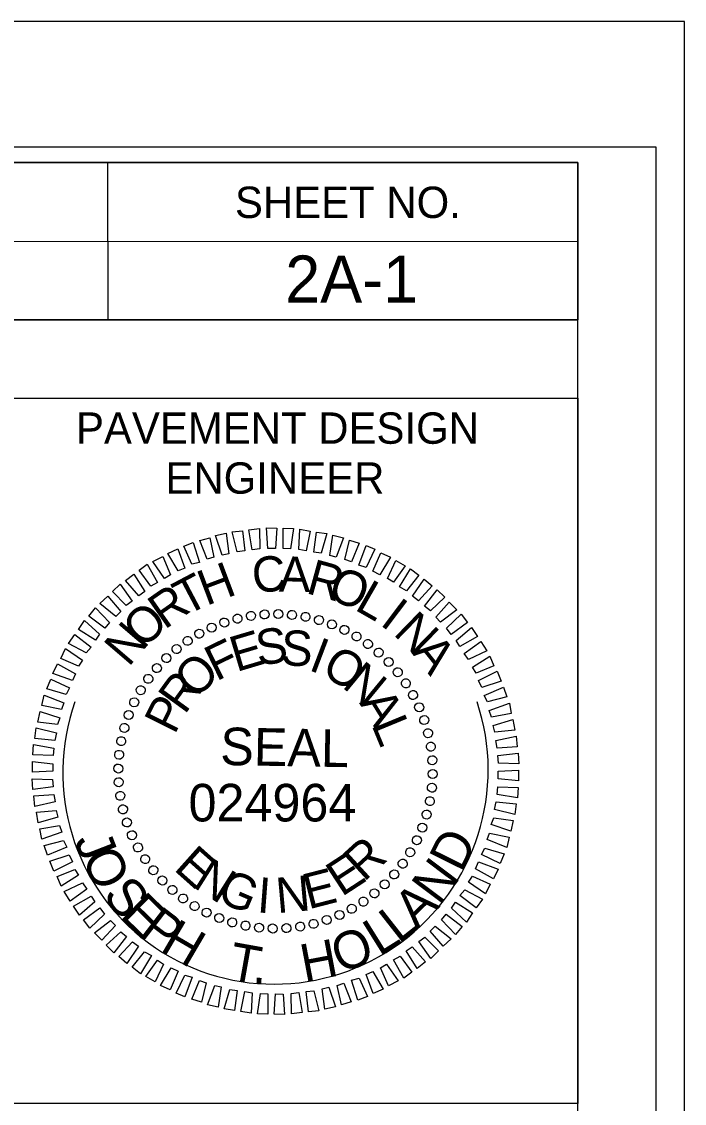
# Model space of a CAD drawing. Extents: x 1640342 to 1730599, y 538663 to 843747.
# Drawn here: x 1730156.25 to 1730177.39, y 540321.41 to 540355.92 of the extents above; entities that cross this region are included whole.
import ezdxf

# ---------------------------------------------------------------- set-up
doc = ezdxf.new("R2010")
doc.units = 0
for name, color, linetype in [('Sheet Data Field CELL', 7, 'Continuous'), ('Sheet PE Seal Cell', 7, 'Continuous'), ('Sheet Plan CELL', 7, 'Continuous'), ('Sheet Plot Border Inside CELL', 7, 'Continuous'), ('Sheet Plot Border Outside CELL', 7, 'Continuous')]:
    doc.layers.add(name, color=color, linetype=linetype)

msp = doc.modelspace()

# ---------------------------------------------------------------- linework, layer by layer
at = {"layer": 'Sheet PE Seal Cell'}
for p, q in [((1730163.569, 540336.956), (1730163.569, 540336.956)), ((1730163.999, 540337.016), (1730163.999, 540337.016)), ((1730164.439, 540337.026), (1730164.439, 540337.026)), ((1730164.879, 540336.996), (1730164.879, 540336.996)), ((1730165.309, 540336.926), (1730165.309, 540336.926)), ((1730162.309, 540336.596), (1730162.309, 540336.596)), ((1730162.709, 540336.756), (1730162.709, 540336.756)), ((1730163.129, 540336.876), (1730163.129, 540336.876)), ((1730165.729, 540336.836), (1730165.729, 540336.836)), ((1730166.149, 540336.696), (1730166.149, 540336.696)), ((1730161.919, 540336.396), (1730161.919, 540336.396)), ((1730166.549, 540336.516), (1730166.549, 540336.516)), ((1730166.939, 540336.316), (1730166.939, 540336.316)), ((1730161.189, 540335.916), (1730161.189, 540335.916)), ((1730161.539, 540336.166), (1730161.539, 540336.166)), ((1730167.299, 540336.066), (1730167.299, 540336.066)), ((1730160.859, 540335.616), (1730160.859, 540335.616)), ((1730167.649, 540335.796), (1730167.649, 540335.796)), ((1730160.559, 540335.306), (1730160.559, 540335.306)), ((1730167.959, 540335.496), (1730167.959, 540335.496)), ((1730160.289, 540334.956), (1730160.289, 540334.956)), ((1730168.259, 540335.166), (1730168.259, 540335.166)), ((1730160.039, 540334.596), (1730160.039, 540334.596)), ((1730168.509, 540334.816), (1730168.509, 540334.816)), ((1730159.839, 540334.206), (1730159.839, 540334.206)), ((1730168.739, 540334.436), (1730168.739, 540334.436)), ((1730168.939, 540334.046), (1730168.939, 540334.046)), ((1730159.659, 540333.806), (1730159.659, 540333.806)), ((1730169.099, 540333.646), (1730169.099, 540333.646)), ((1730159.519, 540333.386), (1730159.519, 540333.386)), ((1730169.219, 540333.226), (1730169.219, 540333.226)), ((1730159.429, 540332.966), (1730159.429, 540332.966)), ((1730169.299, 540332.786), (1730169.299, 540332.786)), ((1730159.359, 540332.536), (1730159.359, 540332.536)), ((1730159.329, 540332.096), (1730159.329, 540332.096)), ((1730169.359, 540332.356), (1730169.359, 540332.356)), ((1730169.369, 540331.916), (1730169.369, 540331.916)), ((1730159.339, 540331.656), (1730159.339, 540331.656)), ((1730169.339, 540331.476), (1730169.339, 540331.476)), ((1730159.399, 540331.226), (1730159.399, 540331.226)), ((1730159.479, 540330.786), (1730159.479, 540330.786)), ((1730169.269, 540331.046), (1730169.269, 540331.046)), ((1730159.599, 540330.366), (1730159.599, 540330.366)), ((1730169.179, 540330.626), (1730169.179, 540330.626)), ((1730169.039, 540330.206), (1730169.039, 540330.206)), ((1730159.759, 540329.966), (1730159.759, 540329.966)), ((1730168.859, 540329.806), (1730168.859, 540329.806)), ((1730159.959, 540329.576), (1730159.959, 540329.576)), ((1730168.659, 540329.416), (1730168.659, 540329.416)), ((1730160.189, 540329.196), (1730160.189, 540329.196)), ((1730168.409, 540329.056), (1730168.409, 540329.056)), ((1730160.439, 540328.846), (1730160.439, 540328.846)), ((1730168.139, 540328.706), (1730168.139, 540328.706)), ((1730160.739, 540328.516), (1730160.739, 540328.516)), ((1730167.839, 540328.396), (1730167.839, 540328.396)), ((1730161.049, 540328.216), (1730161.049, 540328.216)), ((1730161.399, 540327.946), (1730161.399, 540327.946)), ((1730167.509, 540328.096), (1730167.509, 540328.096)), ((1730161.759, 540327.696), (1730161.759, 540327.696)), ((1730166.779, 540327.616), (1730166.779, 540327.616)), ((1730167.159, 540327.846), (1730167.159, 540327.846)), ((1730162.149, 540327.496), (1730162.149, 540327.496)), ((1730162.549, 540327.316), (1730162.549, 540327.316)), ((1730165.989, 540327.256), (1730165.989, 540327.256)), ((1730166.389, 540327.416), (1730166.389, 540327.416)), ((1730162.969, 540327.176), (1730162.969, 540327.176)), ((1730163.389, 540327.086), (1730163.389, 540327.086)), ((1730163.819, 540327.016), (1730163.819, 540327.016)), ((1730164.259, 540326.986), (1730164.259, 540326.986)), ((1730164.699, 540326.996), (1730164.699, 540326.996)), ((1730165.129, 540327.056), (1730165.129, 540327.056)), ((1730165.569, 540327.136), (1730165.569, 540327.136))]:
    msp.add_line(p, q, dxfattribs=at)
for points in [[(1730163.129, 540339.006), (1730162.969, 540339.646), (1730163.299, 540339.676), (1730163.369, 540339.036)], [(1730163.609, 540339.066), (1730163.499, 540339.706), (1730163.839, 540339.746), (1730163.849, 540339.096)], [(1730164.109, 540339.116), (1730164.059, 540339.766), (1730164.389, 540339.756), (1730164.349, 540339.106)], [(1730164.589, 540339.106), (1730164.589, 540339.756), (1730164.919, 540339.746), (1730164.829, 540339.096)], [(1730165.089, 540339.076), (1730165.129, 540339.726), (1730165.459, 540339.666), (1730165.329, 540339.036)], [(1730162.169, 540338.766), (1730161.939, 540339.366), (1730162.249, 540339.456), (1730162.379, 540338.836)], [(1730162.649, 540338.896), (1730162.439, 540339.526), (1730162.779, 540339.596), (1730162.859, 540338.946)], [(1730165.569, 540338.996), (1730165.659, 540339.636), (1730165.989, 540339.586), (1730165.809, 540338.966)], [(1730166.079, 540338.886), (1730166.179, 540339.536), (1730166.519, 540339.456), (1730166.289, 540338.836)], [(1730166.559, 540338.756), (1730166.709, 540339.376), (1730167.019, 540339.276), (1730166.769, 540338.686)], [(1730161.239, 540338.396), (1730160.919, 540338.956), (1730161.229, 540339.096), (1730161.459, 540338.486)], [(1730161.679, 540338.606), (1730161.419, 540339.186), (1730161.719, 540339.306), (1730161.929, 540338.666)], [(1730167.009, 540338.576), (1730167.239, 540339.206), (1730167.519, 540339.086), (1730167.239, 540338.506)], [(1730160.809, 540338.156), (1730160.439, 540338.696), (1730160.749, 540338.856), (1730160.999, 540338.276)], [(1730167.459, 540338.386), (1730167.709, 540338.976), (1730168.019, 540338.836), (1730167.679, 540338.276)], [(1730167.919, 540338.156), (1730168.189, 540338.726), (1730168.489, 540338.556), (1730168.109, 540338.036)], [(1730159.989, 540337.606), (1730159.559, 540338.086), (1730159.829, 540338.296), (1730160.179, 540337.736)], [(1730160.369, 540337.906), (1730159.999, 540338.416), (1730160.259, 540338.606), (1730160.589, 540338.026)], [(1730168.309, 540337.886), (1730168.659, 540338.466), (1730168.919, 540338.256), (1730168.529, 540337.766)], [(1730159.589, 540337.296), (1730159.149, 540337.736), (1730159.389, 540337.976), (1730159.779, 540337.436)], [(1730168.719, 540337.586), (1730169.089, 540338.136), (1730169.349, 540337.916), (1730168.909, 540337.446)], [(1730169.099, 540337.276), (1730169.509, 540337.796), (1730169.749, 540337.556), (1730169.289, 540337.126)], [(1730159.259, 540336.946), (1730158.749, 540337.356), (1730158.999, 540337.586), (1730159.419, 540337.106)], [(1730169.459, 540336.926), (1730169.889, 540337.396), (1730170.129, 540337.156), (1730169.609, 540336.766)], [(1730158.909, 540336.566), (1730158.389, 540336.956), (1730158.609, 540337.216), (1730159.049, 540336.746)], [(1730169.809, 540336.566), (1730170.269, 540337.016), (1730170.479, 540336.746), (1730169.949, 540336.366)], [(1730158.609, 540336.186), (1730158.069, 540336.526), (1730158.259, 540336.816), (1730158.739, 540336.376)], [(1730170.109, 540336.176), (1730170.599, 540336.596), (1730170.789, 540336.306), (1730170.229, 540335.986)], [(1730158.309, 540335.786), (1730157.749, 540336.086), (1730157.949, 540336.366), (1730158.469, 540335.966)], [(1730158.069, 540335.356), (1730157.499, 540335.606), (1730157.649, 540335.916), (1730158.189, 540335.546)], [(1730170.369, 540335.766), (1730170.899, 540336.146), (1730171.089, 540335.846), (1730170.509, 540335.566)], [(1730170.629, 540335.326), (1730171.189, 540335.676), (1730171.319, 540335.366), (1730170.749, 540335.136)], [(1730157.869, 540334.896), (1730157.249, 540335.126), (1730157.399, 540335.436), (1730157.969, 540335.116)], [(1730170.829, 540334.896), (1730171.419, 540335.196), (1730171.549, 540334.876), (1730170.929, 540334.676)], [(1730157.669, 540334.456), (1730157.049, 540334.636), (1730157.179, 540334.946), (1730157.779, 540334.666)], [(1730171.009, 540334.426), (1730171.619, 540334.686), (1730171.729, 540334.376), (1730171.109, 540334.216)], [(1730157.519, 540333.976), (1730156.899, 540334.106), (1730156.969, 540334.436), (1730157.599, 540334.186)], [(1730171.169, 540333.946), (1730171.809, 540334.176), (1730171.869, 540333.846), (1730171.239, 540333.736)], [(1730157.389, 540333.496), (1730156.769, 540333.576), (1730156.839, 540333.916), (1730157.469, 540333.706)], [(1730171.289, 540333.466), (1730171.919, 540333.656), (1730171.979, 540333.316), (1730171.349, 540333.256)], [(1730157.309, 540332.986), (1730156.669, 540333.046), (1730156.709, 540333.386), (1730157.359, 540333.226)], [(1730171.379, 540332.986), (1730172.029, 540333.126), (1730172.059, 540332.786), (1730171.419, 540332.746)], [(1730157.259, 540332.506), (1730156.609, 540332.526), (1730156.629, 540332.856), (1730157.279, 540332.746)], [(1730171.439, 540332.506), (1730172.089, 540332.586), (1730172.109, 540332.246), (1730171.459, 540332.266)], [(1730157.249, 540332.006), (1730156.599, 540331.976), (1730156.599, 540332.316), (1730157.249, 540332.246)], [(1730157.259, 540331.506), (1730156.609, 540331.426), (1730156.589, 540331.766), (1730157.239, 540331.746)], [(1730171.449, 540332.006), (1730172.099, 540332.036), (1730172.099, 540331.696), (1730171.449, 540331.766)], [(1730171.439, 540331.506), (1730172.089, 540331.486), (1730172.069, 540331.156), (1730171.419, 540331.266)], [(1730157.319, 540331.026), (1730156.669, 540330.886), (1730156.639, 540331.226), (1730157.279, 540331.266)], [(1730157.409, 540330.546), (1730156.779, 540330.356), (1730156.719, 540330.696), (1730157.349, 540330.756)], [(1730171.389, 540331.026), (1730172.029, 540330.966), (1730171.989, 540330.626), (1730171.339, 540330.786)], [(1730171.309, 540330.516), (1730171.929, 540330.436), (1730171.859, 540330.096), (1730171.229, 540330.306)], [(1730157.529, 540330.066), (1730156.889, 540329.836), (1730156.829, 540330.166), (1730157.459, 540330.276)], [(1730171.179, 540330.036), (1730171.799, 540329.906), (1730171.729, 540329.576), (1730171.099, 540329.826)], [(1730157.689, 540329.586), (1730157.079, 540329.326), (1730156.969, 540329.636), (1730157.589, 540329.796)], [(1730157.869, 540329.116), (1730157.279, 540328.816), (1730157.149, 540329.136), (1730157.769, 540329.336)], [(1730171.029, 540329.556), (1730171.649, 540329.376), (1730171.519, 540329.066), (1730170.919, 540329.346)], [(1730170.829, 540329.116), (1730171.449, 540328.886), (1730171.299, 540328.576), (1730170.729, 540328.896)], [(1730158.069, 540328.686), (1730157.509, 540328.336), (1730157.379, 540328.646), (1730157.949, 540328.876)], [(1730170.629, 540328.656), (1730171.199, 540328.406), (1730171.049, 540328.096), (1730170.509, 540328.466)], [(1730158.329, 540328.246), (1730157.799, 540327.866), (1730157.609, 540328.166), (1730158.189, 540328.446)], [(1730158.589, 540327.836), (1730158.099, 540327.416), (1730157.909, 540327.706), (1730158.469, 540328.026)], [(1730170.389, 540328.226), (1730170.949, 540327.926), (1730170.749, 540327.646), (1730170.229, 540328.046)], [(1730158.889, 540327.446), (1730158.429, 540326.996), (1730158.219, 540327.266), (1730158.749, 540327.646)], [(1730170.089, 540327.826), (1730170.629, 540327.486), (1730170.439, 540327.196), (1730169.959, 540327.636)], [(1730169.789, 540327.446), (1730170.309, 540327.056), (1730170.089, 540326.796), (1730169.649, 540327.266)], [(1730159.239, 540327.086), (1730158.809, 540326.616), (1730158.569, 540326.856), (1730159.089, 540327.246)], [(1730169.439, 540327.066), (1730169.949, 540326.656), (1730169.699, 540326.426), (1730169.279, 540326.906)], [(1730159.599, 540326.736), (1730159.189, 540326.216), (1730158.949, 540326.456), (1730159.409, 540326.886)], [(1730159.979, 540326.426), (1730159.609, 540325.876), (1730159.349, 540326.096), (1730159.789, 540326.566)], [(1730169.109, 540326.716), (1730169.549, 540326.276), (1730169.309, 540326.036), (1730168.919, 540326.576)], [(1730160.389, 540326.126), (1730160.039, 540325.546), (1730159.779, 540325.756), (1730160.169, 540326.246)], [(1730168.709, 540326.406), (1730169.139, 540325.926), (1730168.869, 540325.716), (1730168.519, 540326.276)], [(1730160.779, 540325.856), (1730160.509, 540325.286), (1730160.209, 540325.456), (1730160.589, 540325.976)], [(1730168.329, 540326.106), (1730168.699, 540325.596), (1730168.439, 540325.406), (1730168.109, 540325.986)], [(1730161.239, 540325.626), (1730160.989, 540325.036), (1730160.679, 540325.176), (1730161.019, 540325.736)], [(1730167.459, 540325.616), (1730167.779, 540325.056), (1730167.469, 540324.916), (1730167.239, 540325.526)], [(1730167.889, 540325.856), (1730168.259, 540325.316), (1730167.949, 540325.156), (1730167.699, 540325.736)], [(1730161.689, 540325.436), (1730161.459, 540324.806), (1730161.179, 540324.926), (1730161.459, 540325.506)], [(1730162.139, 540325.256), (1730161.989, 540324.636), (1730161.679, 540324.736), (1730161.929, 540325.326)], [(1730166.529, 540325.246), (1730166.759, 540324.646), (1730166.449, 540324.556), (1730166.319, 540325.176)], [(1730167.019, 540325.406), (1730167.279, 540324.826), (1730166.979, 540324.706), (1730166.769, 540325.346)], [(1730162.619, 540325.126), (1730162.519, 540324.476), (1730162.179, 540324.556), (1730162.409, 540325.176)], [(1730163.129, 540325.016), (1730163.039, 540324.376), (1730162.709, 540324.426), (1730162.889, 540325.046)], [(1730163.609, 540324.936), (1730163.569, 540324.286), (1730163.239, 540324.346), (1730163.369, 540324.976)], [(1730164.109, 540324.906), (1730164.109, 540324.256), (1730163.779, 540324.266), (1730163.869, 540324.916)], [(1730164.589, 540324.896), (1730164.639, 540324.246), (1730164.309, 540324.256), (1730164.349, 540324.906)], [(1730165.089, 540324.946), (1730165.199, 540324.306), (1730164.859, 540324.266), (1730164.849, 540324.916)], [(1730165.569, 540325.006), (1730165.729, 540324.366), (1730165.399, 540324.336), (1730165.329, 540324.976)], [(1730166.049, 540325.116), (1730166.259, 540324.486), (1730165.919, 540324.416), (1730165.839, 540325.066)]]:
    msp.add_lwpolyline(points, close=True, dxfattribs=at)
for centre, major_axis in [((1730163.136, 540336.873), (-0.035, 0.14)), ((1730163.565, 540336.96), (-0.023, 0.142)), ((1730163.999, 540337.009), (-0.01, 0.144)), ((1730164.437, 540337.021), (0.003, 0.144)), ((1730164.874, 540336.994), (0.015, 0.143)), ((1730165.306, 540336.93), (0.027, 0.141)), ((1730165.732, 540336.827), (0.04, 0.138)), ((1730162.309, 540336.588), (-0.059, 0.132)), ((1730162.716, 540336.748), (-0.047, 0.136)), ((1730166.147, 540336.689), (0.052, 0.134)), ((1730166.548, 540336.514), (0.063, 0.129)), ((1730161.544, 540336.164), (-0.081, 0.119)), ((1730161.918, 540336.393), (-0.07, 0.126)), ((1730166.933, 540336.305), (0.074, 0.123)), ((1730167.298, 540336.064), (0.085, 0.116)), ((1730161.193, 540335.904), (-0.091, 0.112)), ((1730167.64, 540335.791), (0.094, 0.109)), ((1730160.865, 540335.614), (-0.1, 0.104)), ((1730167.958, 540335.49), (0.104, 0.1)), ((1730160.564, 540335.296), (-0.109, 0.094)), ((1730168.247, 540335.162), (0.112, 0.091)), ((1730160.291, 540334.954), (-0.116, 0.085)), ((1730168.508, 540334.811), (0.119, 0.081)), ((1730160.05, 540334.589), (-0.123, 0.074)), ((1730168.736, 540334.438), (0.126, 0.07)), ((1730159.841, 540334.205), (-0.129, 0.063)), ((1730168.932, 540334.046), (0.132, 0.059)), ((1730159.666, 540333.803), (-0.134, 0.052)), ((1730159.528, 540333.388), (-0.138, 0.04)), ((1730169.092, 540333.639), (0.136, 0.047)), ((1730159.425, 540332.963), (-0.141, 0.027)), ((1730169.216, 540333.219), (0.14, 0.035)), ((1730169.304, 540332.79), (0.142, 0.023)), ((1730159.361, 540332.53), (-0.143, 0.015)), ((1730169.353, 540332.356), (0.144, 0.01)), ((1730159.334, 540332.093), (-0.144, 0.003)), ((1730159.346, 540331.656), (-0.144, -0.01)), ((1730169.365, 540331.918), (0.144, -0.003)), ((1730169.338, 540331.481), (0.143, -0.015)), ((1730159.395, 540331.221), (-0.142, -0.023)), ((1730169.273, 540331.049), (0.141, -0.027)), ((1730159.482, 540330.792), (-0.14, -0.035)), ((1730169.171, 540330.623), (0.138, -0.04)), ((1730159.607, 540330.373), (-0.136, -0.047)), ((1730169.032, 540330.208), (0.134, -0.052)), ((1730159.767, 540329.965), (-0.132, -0.059)), ((1730159.962, 540329.574), (-0.126, -0.07)), ((1730168.858, 540329.807), (0.129, -0.063)), ((1730160.191, 540329.201), (-0.119, -0.081)), ((1730168.649, 540329.422), (0.123, -0.074)), ((1730160.451, 540328.849), (-0.112, -0.091)), ((1730168.407, 540329.057), (0.116, -0.085)), ((1730160.741, 540328.521), (-0.104, -0.1)), ((1730168.135, 540328.715), (0.109, -0.094)), ((1730161.059, 540328.22), (-0.094, -0.109)), ((1730167.834, 540328.397), (0.1, -0.104)), ((1730161.401, 540327.948), (-0.085, -0.116)), ((1730167.154, 540327.847), (0.081, -0.119)), ((1730167.506, 540328.108), (0.091, -0.112)), ((1730161.766, 540327.706), (-0.074, -0.123)), ((1730162.15, 540327.497), (-0.063, -0.129)), ((1730166.781, 540327.619), (0.07, -0.126)), ((1730162.552, 540327.323), (-0.052, -0.134)), ((1730162.967, 540327.184), (-0.04, -0.138)), ((1730165.563, 540327.139), (0.035, -0.14)), ((1730165.982, 540327.263), (0.047, -0.136)), ((1730166.39, 540327.423), (0.059, -0.132)), ((1730163.392, 540327.082), (-0.027, -0.141)), ((1730163.825, 540327.017), (-0.015, -0.143)), ((1730164.262, 540326.99), (-0.003, -0.144)), ((1730164.699, 540327.002), (0.01, -0.144)), ((1730165.134, 540327.051), (0.023, -0.142))]:
    msp.add_ellipse(centre, major_axis=major_axis, ratio=0.999708, dxfattribs=at)
at = {"layer": 'Sheet Plan CELL'}
for p, q in [((1730158.985, 540351.407), (1730158.995, 540346.407)), ((1730133.98, 540348.912), (1730173.99, 540348.909)), ((1730133.983, 540346.404), (1730173.99, 540346.409)), ((1730133.983, 540346.404), (1730173.99, 540346.409))]:
    msp.add_line(p, q, dxfattribs=at)
for points in [[(1730173.998, 540351.419), (1729873.99, 540351.419), (1729873.99, 540141.419), (1730173.993, 540141.419)], [(1730133.983, 540351.422), (1730173.998, 540351.419), (1730173.99, 540346.409), (1730133.983, 540346.404)], [(1730153.993, 540343.907), (1730173.99, 540343.909), (1730173.993, 540321.407), (1730153.993, 540321.404)]]:
    msp.add_lwpolyline(points, close=True, dxfattribs=at)
at = {"layer": 'Sheet Plot Border Inside CELL'}
msp.add_lwpolyline([(1729843.293, 540140.917), (1730176.49, 540140.919), (1730176.493, 540351.917), (1729843.293, 540351.917)], close=True, dxfattribs=at)
at = {"layer": 'Sheet Plot Border Outside CELL'}
msp.add_lwpolyline([(1729840.693, 540136.917), (1730177.393, 540136.917), (1730177.393, 540355.917), (1729840.693, 540355.917)], close=True, dxfattribs=at)
msp.add_ellipse((1730164.349, 540332.006), major_axis=(4.509, 5.104), ratio=0.993455, start_param=1.958957, end_param=5.764947, dxfattribs=at)

# ---------------------------------------------------------------- texts
at = {"layer": 'Sheet Data Field CELL'}
msp.add_text('2A-1', height=1.5, rotation=0, dxfattribs=at).set_placement((1730164.66, 540346.957))
at = {"layer": 'Sheet PE Seal Cell'}
for s, height, rotation, p in [('H', 1.128, 20.6195, (1730162.139, 540337.276)), ('C', 1.128, 6.2199, (1730163.659, 540337.676)), ('A', 1.128, 359.0203, (1730164.449, 540337.736)), ('R', 1.128, 344.6211, (1730165.289, 540337.696)), ('T', 1.128, 27.8198, (1730161.489, 540336.946)), ('O', 1.128, 337.4212, (1730165.959, 540337.546)), ('L', 1.128, 330.2209, (1730166.839, 540337.176)), ('R', 1.128, 35.0205, (1730160.809, 540336.506)), ('O', 1.128, 42.2217, (1730160.119, 540335.886)), ('I', 1.128, 323.0201, (1730167.649, 540336.696)), ('N', 1.128, 315.8189, (1730168.079, 540336.386)), ('N', 1.128, 49.4235, (1730159.659, 540335.306)), ('S', 1.128, 7.2556, (1730163.789, 540335.376)), ('F', 1.128, 25.967, (1730162.459, 540334.866)), ('E', 1.128, 16.6111, (1730163.099, 540335.166)), ('S', 1.128, 357.9004, (1730164.509, 540335.386)), ('I', 1.128, 339.1896, (1730165.369, 540335.246)), ('O', 1.128, 329.8335, (1730165.769, 540335.106)), ('A', 1.128, 308.6172, (1730168.669, 540335.796)), ('O', 1.128, 44.6812, (1730161.799, 540334.276)), ('N', 1.128, 320.4766, (1730166.439, 540334.706)), ('R', 1.128, 54.0397, (1730161.449, 540333.786)), ('P', 1.128, 63.3989, (1730161.129, 540333.146)), ('A', 1.128, 301.7603, (1730167.009, 540334.186)), ('L', 1.128, 292.4008, (1730167.399, 540333.496)), ('SEAL', 1.1996, 359, (1730162.579, 540332.206)), ('D', 1.2, 63.6039, (1730170.285, 540328.74)), ('J', 1.2, 291.2124, (1730157.911, 540329.799)), ('R', 1.128, 42.4814, (1730167.169, 540328.456)), ('O', 1.2, 296.4669, (1730158.135, 540329.222)), ('E', 1.128, 318.2769, (1730161.069, 540328.876)), ('E', 1.128, 33.1241, (1730166.459, 540327.986)), ('N', 1.128, 327.634, (1730161.669, 540328.336)), ('N', 1.2, 53.0513, (1730169.575, 540327.697)), ('G', 1.128, 336.9902, (1730162.429, 540327.886)), ('N', 1.128, 5.0564, (1730164.409, 540327.476)), ('E', 1.128, 14.4118, (1730165.399, 540327.596)), ('S', 1.2, 308.0413, (1730158.806, 540328.041)), ('I', 1.128, 355.7012, (1730163.739, 540327.506)), ('E', 1.2, 315.3853, (1730159.35, 540327.372)), ('A', 1.2, 44.3588, (1730168.854, 540326.948)), ('P', 1.2, 322.5143, (1730159.955, 540326.794)), ('L', 1.2, 38.1871, (1730168.277, 540326.486)), ('H', 1.2, 329.641, (1730160.627, 540326.296)), ('L', 1.2, 32.0108, (1730167.655, 540326.089)), ('O', 1.2, 20.6113, (1730166.41, 540325.542)), ('H', 1.2, 10.7371, (1730165.267, 540325.276)), ('T', 1.2, 349.8271, (1730162.805, 540325.376)), ('.', 1.2, 356.6032, (1730163.595, 540325.245))]:
    msp.add_text(s, height=height, rotation=rotation, dxfattribs=at).set_placement(p)
msp.add_text('024964', height=1.1996, dxfattribs=at).set_placement((1730161.574, 540330.404))
at = {"layer": 'Sheet Plan CELL'}
for s, height, p in [('SHEET NO.', 1, (1730163.055, 540349.654)), ('PAVEMENT DESIGN', 1.00002, (1730157.984, 540342.452)), ('ENGINEER', 1, (1730160.838, 540340.859))]:
    msp.add_text(s, height=height, rotation=0, dxfattribs=at).set_placement(p)

doc.saveas('drawing.dxf')
